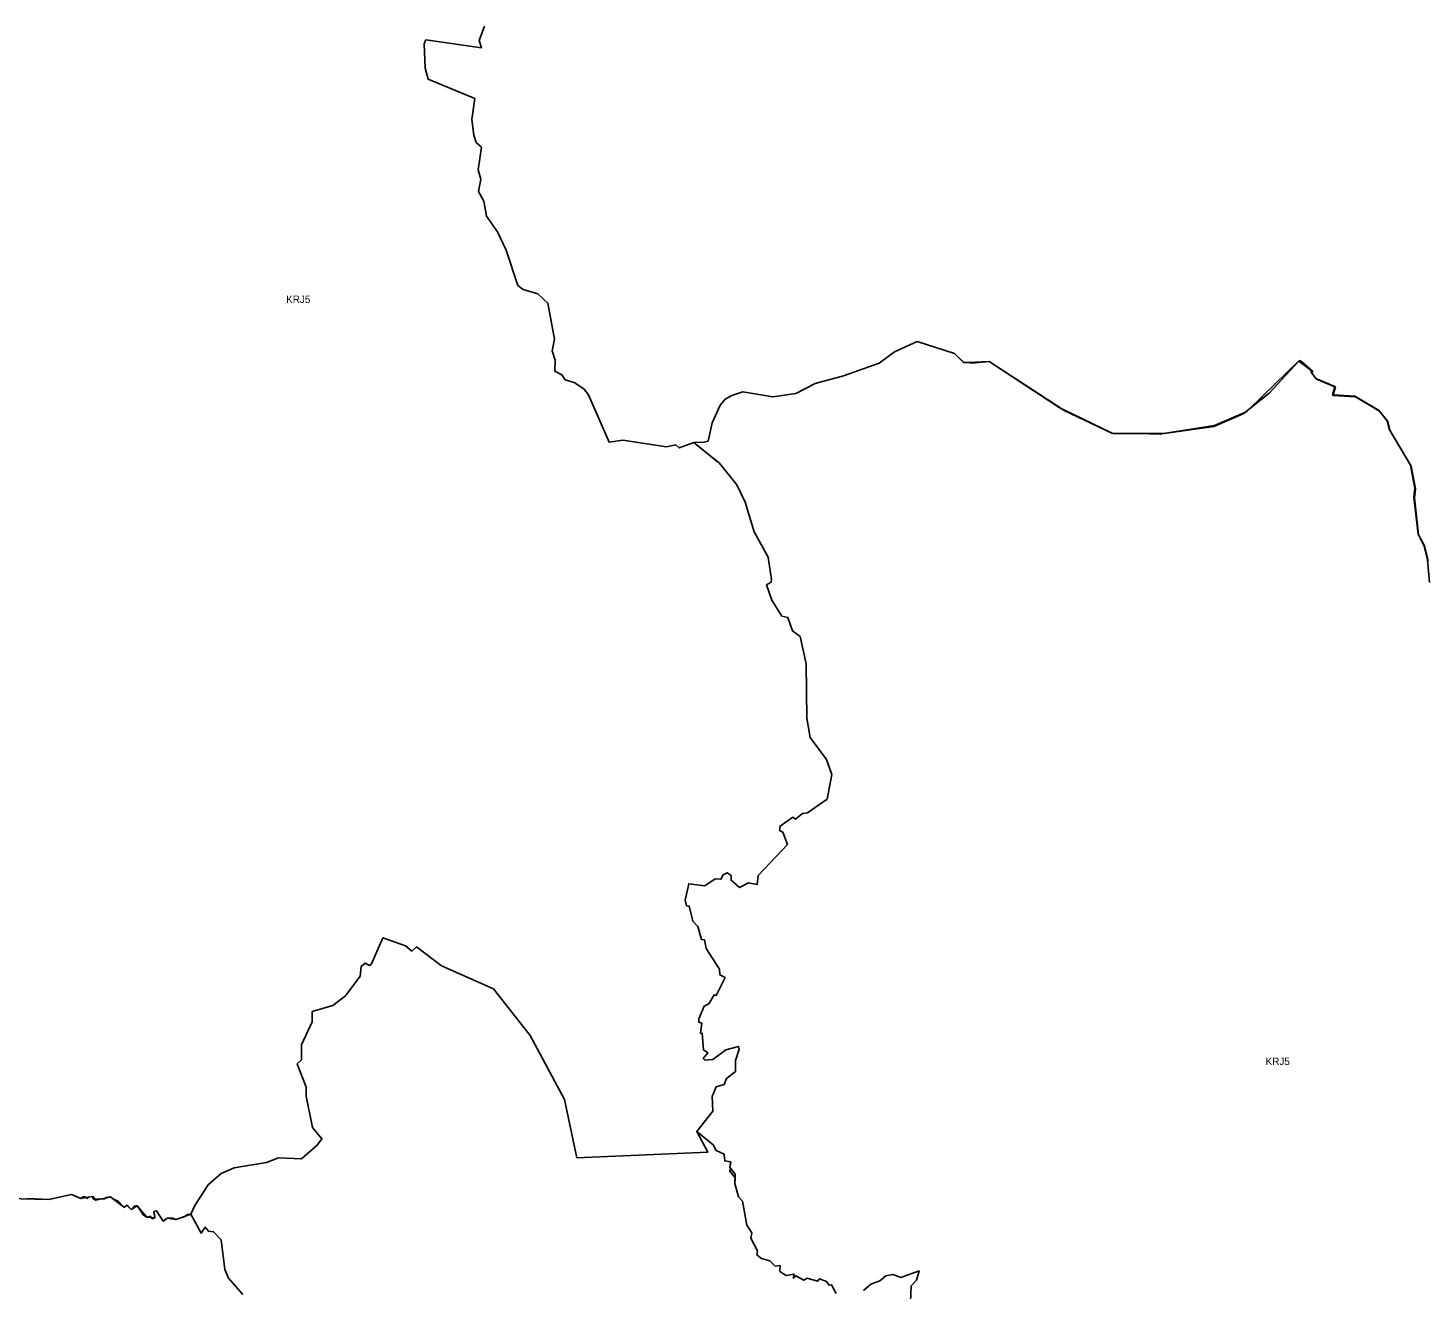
# Model space of a CAD drawing. Extents: x -563112 to -465432, y -1206259 to -1132144.
# Drawn here: x -497026 to -487557, y -1169132 to -1160601 of the extents above; entities that cross this region are included whole.
import ezdxf

# ---------------------------------------------------------------- set-up
doc = ezdxf.new("R2010")
doc.units = 0
doc.layers.add('krajiny', color=7, linetype='Continuous')

msp = doc.modelspace()

# ---------------------------------------------------------------- linework, layer by layer
at = {"layer": 'krajiny'}
for points in [[(-493937.85, -1160588.09), (-493973.85, -1160686.09), (-493959.85, -1160736.09), (-494335.14, -1160681.66), (-494345.85, -1160708.09), (-494338.85, -1160872.09), (-494319.85, -1160947.09), (-494002.85, -1161078.09), (-494023.85, -1161219.09), (-494009.85, -1161325.09), (-493993.85, -1161375.09), (-493958.85, -1161408.09), (-493981.85, -1161561.09), (-493962.85, -1161624.09), (-493979.85, -1161706.09), (-493942.85, -1161773.09), (-493923.85, -1161874.09), (-493850.95, -1161978.87), (-493792.74, -1162102.87), (-493713.16, -1162342.11), (-493676.27, -1162369.55), (-493576.66, -1162399.21), (-493509.97, -1162462.23), (-493464.03, -1162706.51), (-493480.53, -1162785.02), (-493460.61, -1162848.95), (-493463.01, -1162923.08), (-493414.33, -1162946.34), (-493393.49, -1162981.48), (-493332.46, -1162999.29), (-493267.14, -1163041.27), (-493235.27, -1163082.09), (-493095.04, -1163403.38), (-493001.9, -1163389.77), (-492708, -1163434.77), (-492644.87, -1163420.57), (-492620.67, -1163441.96), (-492522.31, -1163406.24), (-492507.27, -1163418.3), (-492425.99, -1163483.44), (-492372.72, -1163526.14), (-492351.44, -1163543.2), (-492230.83, -1163691.37), (-492175, -1163808.83), (-492113.56, -1164010.4), (-492019.9, -1164180.2), (-491996.92, -1164332.66), (-491999.73, -1164350.87), (-492031.12, -1164368.49), (-491994.07, -1164471.21), (-491927.3, -1164579.57), (-491885.76, -1164588.39), (-491854.99, -1164679.59), (-491803.95, -1164718.37), (-491762.32, -1164901.64), (-491758.79, -1165270.97), (-491735.03, -1165401.47), (-491626.32, -1165550.5), (-491589.14, -1165651.61), (-491621.71, -1165817.33), (-491752.92, -1165910.61), (-491787.11, -1165914.44), (-491833.93, -1165953.61), (-491852.71, -1165940.56), (-491939.65, -1166000.07), (-491942.11, -1166030.42), (-491920.38, -1166040.46), (-491889.7, -1166124.05), (-492087.31, -1166334.15), (-492094.04, -1166395.3), (-492153.04, -1166384.23), (-492212.68, -1166415.59), (-492270.17, -1166366.96), (-492269.94, -1166335.74), (-492297.15, -1166315.73), (-492325.16, -1166329.15), (-492339.39, -1166360.22), (-492377.57, -1166358.27), (-492448.23, -1166404.39), (-492556.51, -1166390.79), (-492580.9, -1166502.36), (-492572.26, -1166538.81), (-492553.62, -1166541.13), (-492529.53, -1166642.54), (-492495.94, -1166680.51), (-492471.63, -1166768.38), (-492449.66, -1166770.42), (-492438.27, -1166827.88), (-492349.38, -1166968.65), (-492346.74, -1167006.58), (-492311.56, -1167024.74), (-492371.29, -1167146.31), (-492384.36, -1167141.84), (-492421.47, -1167202.68), (-492453.33, -1167217.69), (-492487.8, -1167305.28), (-492488.76, -1167327.07), (-492468.55, -1167334.17), (-492476.65, -1167403.15), (-492465.98, -1167401.34), (-492457.25, -1167514.53), (-492427.15, -1167533.43), (-492458.58, -1167572.82), (-492448, -1167584.55), (-492393.32, -1167579.39), (-492306.51, -1167514.22), (-492219.47, -1167491.73), (-492216.32, -1167510.21), (-492240.47, -1167585.15), (-492240.88, -1167661.15), (-492302.54, -1167708.1), (-492318.18, -1167747.86), (-492370.41, -1167765.04), (-492398.45, -1167829.81), (-492393.28, -1167928.75), (-492503.38, -1168067.19), (-492428.69, -1168206.68), (-493313.36, -1168243.98), (-493397.24, -1167850.1), (-493630.65, -1167416.1), (-493878.65, -1167102.45), (-494230.26, -1166946.32), (-494398.21, -1166817.49), (-494430.71, -1166845.87), (-494473.8, -1166810.76), (-494625.82, -1166756.83), (-494703.02, -1166931.81), (-494716.54, -1166942.77), (-494745.54, -1166927.65), (-494773.5, -1166949.91), (-494778.32, -1167014.69), (-494877.85, -1167148.61), (-494963.39, -1167213.89), (-495104, -1167255.84), (-495103.97, -1167325.71), (-495176.06, -1167479.77), (-495177.25, -1167581.31), (-495205.36, -1167608.14), (-495144.78, -1167767.7), (-495145.69, -1167827.25), (-495102.62, -1168039.57), (-495038.23, -1168115.41), (-495069.38, -1168159.76), (-495175.35, -1168251.1), (-495330.81, -1168245.87), (-495412.89, -1168275.38), (-495631.46, -1168312.55), (-495719.31, -1168350), (-495808.49, -1168427.29), (-495897.35, -1168566.74), (-495923.87, -1168625.59), (-495948.33, -1168629.17), (-495966.84, -1168640.88), (-495969.92, -1168642.83), (-496006.42, -1168655.58), (-496026.91, -1168662.26), (-496045.93, -1168652.39), (-496056.54, -1168652.09), (-496085.17, -1168654.02), (-496094.39, -1168662.79), (-496112.7, -1168672.6), (-496156.94, -1168602.8), (-496174.26, -1168607.05), (-496171.34, -1168629), (-496168.05, -1168650.88), (-496185.55, -1168656.8), (-496191.94, -1168648.68), (-496198.68, -1168640.13), (-496221.75, -1168645.94), (-496246.48, -1168630.92), (-496262.61, -1168605.73), (-496287.33, -1168568.81), (-496296.52, -1168569.81), (-496309.11, -1168571.17), (-496327.82, -1168593.74), (-496349.96, -1168569.23), (-496355, -1168566.19), (-496356.97, -1168565), (-496375.79, -1168580.16), (-496380.47, -1168576.54), (-496380.53, -1168576.47), (-496416.39, -1168537.81), (-496447.95, -1168524.05), (-496456.56, -1168520.3), (-496467.35, -1168508.97), (-496499.42, -1168512.83), (-496503, -1168516.67), (-496507.88, -1168521.89), (-496526.46, -1168521.73), (-496534.37, -1168521.66), (-496561.51, -1168523.91), (-496567.7, -1168530.63), (-496587.01, -1168519.83), (-496586.68, -1168506.57), (-496617.69, -1168511.48), (-496617.78, -1168511.55), (-496628.15, -1168519.69), (-496634.15, -1168514.17), (-496640.07, -1168508.73), (-496652.34, -1168508.13), (-496668.1, -1168519.61), (-496731.55, -1168492.58), (-496885.21, -1168526.4), (-497029.54, -1168520.63)], [(-487547.03, -1164352.52), (-487560.1, -1164197.94), (-487585.25, -1164099.56), (-487623.83, -1164024.27), (-487651.73, -1163775.54), (-487645.06, -1163713.8), (-487674.29, -1163559.34), (-487819.32, -1163316.01), (-487832.6, -1163259.04), (-487884.25, -1163192.56), (-487888.03, -1163187.69), (-488051.52, -1163091.98), (-488197.27, -1163083.46), (-488202.35, -1163083.16), (-488187.78, -1163028.69), (-488187, -1163025.76), (-488314.55, -1162971.2), (-488348.53, -1162927.5), (-488340.23, -1162922.6), (-488338.77, -1162921.74), (-488411.75, -1162857.61), (-488425.74, -1162850.44), (-488429.52, -1162854.51), (-488630.24, -1163070.76), (-488763.09, -1163176.36), (-488791.58, -1163199), (-488807.04, -1163211.29), (-489004.27, -1163295.82), (-489342.39, -1163345.13), (-489346.21, -1163345.13), (-489517.4, -1163345.13), (-489684.77, -1163345.13), (-489692.88, -1163341.23), (-490032.92, -1163177.75), (-490051.07, -1163169.03), (-490525.81, -1162856.95), (-490641.01, -1162867.77), (-490667.95, -1162864.87), (-490699.35, -1162861.5), (-490760.55, -1162803.82), (-491012, -1162721.99), (-491165.21, -1162792.09), (-491268.75, -1162867.85), (-491509.96, -1162954.32), (-491702.03, -1163006.32), (-491831.58, -1163074.25), (-491988.33, -1163097.32), (-492191.89, -1163062.85), (-492265.34, -1163087.88), (-492310.71, -1163111.47), (-492344.96, -1163153.08), (-492398.4, -1163271.65), (-492425.04, -1163395.59), (-492453.57, -1163403.79), (-492522.31, -1163406.24), (-492620.67, -1163441.96), (-492644.87, -1163420.57), (-492708, -1163434.77), (-493001.9, -1163389.77), (-493095.04, -1163403.38), (-493235.27, -1163082.09), (-493267.14, -1163041.27), (-493332.46, -1162999.29), (-493393.49, -1162981.48), (-493414.33, -1162946.34), (-493463.01, -1162923.08), (-493460.61, -1162848.95), (-493480.53, -1162785.02), (-493464.03, -1162706.51), (-493509.97, -1162462.23), (-493576.66, -1162399.21), (-493676.27, -1162369.55), (-493713.16, -1162342.11), (-493792.74, -1162102.87), (-493850.95, -1161978.87), (-493923.85, -1161874.09), (-493942.85, -1161773.09), (-493979.85, -1161706.09), (-493962.85, -1161624.09), (-493981.85, -1161561.09), (-493958.85, -1161408.09), (-493993.85, -1161375.09), (-494009.85, -1161325.09), (-494023.85, -1161219.09), (-494002.85, -1161078.09), (-494319.85, -1160947.09), (-494338.85, -1160872.09), (-494345.85, -1160708.09), (-494335.14, -1160681.66), (-493959.85, -1160736.09), (-493973.85, -1160686.09), (-493937.85, -1160588.09)], [(-491559.92, -1169162.48), (-491590.51, -1169103.48), (-491607.97, -1169105.14), (-491625.55, -1169080.64), (-491672.12, -1169062.82), (-491685.92, -1169079.68), (-491755.54, -1169059.29), (-491779.37, -1169072.63), (-491833.21, -1169042), (-491850.05, -1169058.87), (-491844.35, -1169031.47), (-491897.55, -1169041.78), (-491939.9, -1169013.64), (-491937.54, -1168973.52), (-491971.36, -1168976.6), (-492008.14, -1168940.72), (-492065.21, -1168924.97), (-492095.78, -1168900.38), (-492091.96, -1168873.22), (-492137.63, -1168789.05), (-492129.86, -1168751.37), (-492163.79, -1168699.46), (-492193.52, -1168538.6), (-492221.05, -1168508.86), (-492245.48, -1168419.2), (-492243.08, -1168355.51), (-492278.15, -1168309.88), (-492272.79, -1168271.82), (-492313.08, -1168265.49), (-492317.03, -1168220.32), (-492371.54, -1168194.73), (-492391.49, -1168156.83), (-492503.38, -1168067.19), (-492393.28, -1167928.75), (-492398.45, -1167829.81), (-492370.41, -1167765.04), (-492318.18, -1167747.86), (-492302.54, -1167708.1), (-492240.88, -1167661.15), (-492240.47, -1167585.15), (-492216.32, -1167510.21), (-492219.47, -1167491.73), (-492306.51, -1167514.22), (-492393.32, -1167579.39), (-492448, -1167584.55), (-492458.58, -1167572.82), (-492427.15, -1167533.43), (-492457.25, -1167514.53), (-492465.98, -1167401.34), (-492476.65, -1167403.15), (-492468.55, -1167334.17), (-492488.76, -1167327.07), (-492487.8, -1167305.28), (-492453.33, -1167217.69), (-492421.47, -1167202.68), (-492384.36, -1167141.84), (-492371.29, -1167146.31), (-492311.56, -1167024.74), (-492346.74, -1167006.58), (-492349.38, -1166968.65), (-492438.27, -1166827.88), (-492449.66, -1166770.42), (-492471.63, -1166768.38), (-492495.94, -1166680.51), (-492529.53, -1166642.54), (-492553.62, -1166541.13), (-492572.26, -1166538.81), (-492580.9, -1166502.36), (-492556.51, -1166390.79), (-492448.23, -1166404.39), (-492377.57, -1166358.27), (-492339.39, -1166360.22), (-492325.16, -1166329.15), (-492297.15, -1166315.73), (-492269.94, -1166335.74), (-492270.17, -1166366.96), (-492212.68, -1166415.59), (-492153.04, -1166384.23), (-492094.04, -1166395.3), (-492087.31, -1166334.15), (-491889.7, -1166124.05), (-491920.38, -1166040.46), (-491942.11, -1166030.42), (-491939.65, -1166000.07), (-491852.71, -1165940.56), (-491833.93, -1165953.61), (-491787.11, -1165914.44), (-491752.92, -1165910.61), (-491621.71, -1165817.33), (-491589.14, -1165651.61), (-491626.32, -1165550.5), (-491735.03, -1165401.47), (-491758.79, -1165270.97), (-491762.32, -1164901.64), (-491803.95, -1164718.37), (-491854.99, -1164679.59), (-491885.76, -1164588.39), (-491927.3, -1164579.57), (-491994.07, -1164471.21), (-492031.12, -1164368.49), (-491999.73, -1164350.87), (-491996.92, -1164332.66), (-492019.9, -1164180.2), (-492113.56, -1164010.4), (-492175, -1163808.83), (-492230.83, -1163691.37), (-492351.44, -1163543.2), (-492425.99, -1163483.44), (-492522.31, -1163406.24), (-492453.57, -1163403.79), (-492425.04, -1163395.59), (-492398.4, -1163271.65), (-492344.96, -1163153.08), (-492310.71, -1163111.47), (-492265.34, -1163087.88), (-492191.89, -1163062.85), (-491988.33, -1163097.32), (-491831.58, -1163074.25), (-491702.03, -1163006.32), (-491509.96, -1162954.32), (-491268.75, -1162867.85), (-491165.21, -1162792.09), (-491012, -1162721.99), (-490760.55, -1162803.82), (-490695.5, -1162866.41), (-490667.95, -1162864.87), (-490525.81, -1162856.95), (-490032.92, -1163177.75), (-490017.75, -1163187.63), (-489696.07, -1163341.16), (-489692.88, -1163341.23), (-489517.4, -1163345.13), (-489367.08, -1163348.47), (-489346.21, -1163345.13), (-489001.53, -1163289.98), (-488791.58, -1163199), (-488782.21, -1163194.94), (-488763.09, -1163176.36), (-488430.89, -1162853.46), (-488429.52, -1162854.51), (-488340.23, -1162922.6), (-488334.92, -1162926.65), (-488344.68, -1162932.41), (-488314.53, -1162971.21), (-488310.73, -1162976.1), (-488187.78, -1163028.69), (-488183.15, -1163030.67), (-488197.27, -1163083.46), (-488198.5, -1163088.07), (-488047.67, -1163096.89), (-487884.25, -1163192.56), (-487884.18, -1163192.6), (-487828.75, -1163263.95), (-487815.47, -1163320.92), (-487670.44, -1163564.25), (-487641.21, -1163718.71), (-487647.88, -1163780.45), (-487619.98, -1164029.18), (-487581.4, -1164104.47), (-487556.25, -1164202.85)], [(-495573.82, -1169170.31), (-495668.9, -1169058.49), (-495695.33, -1168999.11), (-495720.22, -1168799.7), (-495772.52, -1168744.9), (-495805.63, -1168741.48), (-495827.58, -1168713.7), (-495855.56, -1168754.61), (-495923.87, -1168625.59), (-495897.35, -1168566.74), (-495808.49, -1168427.29), (-495719.31, -1168350), (-495631.46, -1168312.55), (-495412.89, -1168275.38), (-495330.81, -1168245.87), (-495175.35, -1168251.1), (-495069.38, -1168159.76), (-495038.23, -1168115.41), (-495102.62, -1168039.57), (-495145.69, -1167827.25), (-495144.78, -1167767.7), (-495205.36, -1167608.14), (-495177.25, -1167581.31), (-495176.06, -1167479.77), (-495103.97, -1167325.71), (-495104, -1167255.84), (-494963.39, -1167213.89), (-494877.85, -1167148.61), (-494778.32, -1167014.69), (-494773.5, -1166949.91), (-494745.54, -1166927.65), (-494716.54, -1166942.77), (-494703.02, -1166931.81), (-494625.82, -1166756.83), (-494473.8, -1166810.76), (-494430.71, -1166845.87), (-494398.21, -1166817.49), (-494230.26, -1166946.32), (-493878.65, -1167102.45), (-493630.65, -1167416.1), (-493397.24, -1167850.1), (-493313.36, -1168243.98), (-492428.69, -1168206.68), (-492503.38, -1168067.19), (-492391.49, -1168156.83), (-492371.54, -1168194.73), (-492317.03, -1168220.32), (-492313.08, -1168265.49), (-492272.79, -1168271.82), (-492278.15, -1168309.88), (-492274.76, -1168314.3), (-492243.08, -1168355.51), (-492243.99, -1168379.54), (-492245.48, -1168419.2), (-492221.05, -1168508.86), (-492193.52, -1168538.6), (-492163.79, -1168699.46), (-492129.86, -1168751.37), (-492137.63, -1168789.05), (-492091.96, -1168873.22), (-492095.78, -1168900.38), (-492065.21, -1168924.97), (-492008.14, -1168940.72), (-491971.36, -1168976.6), (-491937.54, -1168973.52), (-491939.9, -1169013.64), (-491897.55, -1169041.78), (-491844.35, -1169031.47), (-491850.05, -1169058.87), (-491833.21, -1169042), (-491779.37, -1169072.63), (-491755.54, -1169059.29), (-491685.92, -1169079.68), (-491672.12, -1169062.82), (-491625.55, -1169080.64), (-491607.97, -1169105.14), (-491590.51, -1169103.48), (-491559.92, -1169162.48)], [(-497168.1, -1168520.63), (-496885.21, -1168526.4), (-496731.55, -1168492.58), (-496668.1, -1168519.61), (-496634.15, -1168514.17), (-496617.78, -1168511.55), (-496586.68, -1168506.57), (-496567.7, -1168530.63), (-496526.46, -1168521.73), (-496503, -1168516.67), (-496467.35, -1168508.97), (-496447.95, -1168524.05), (-496380.53, -1168576.47), (-496375.79, -1168580.16), (-496356.97, -1168565), (-496327.82, -1168593.74), (-496287.33, -1168568.81), (-496221.75, -1168645.94), (-496191.94, -1168648.68), (-496168.05, -1168650.88), (-496174.26, -1168607.05), (-496156.94, -1168602.8), (-496112.7, -1168672.6), (-496085.17, -1168654.02), (-496026.91, -1168662.26), (-495966.84, -1168640.88), (-495923.87, -1168625.59), (-495855.56, -1168754.61), (-495827.58, -1168713.7), (-495805.63, -1168741.48), (-495772.52, -1168744.9), (-495720.22, -1168799.7), (-495695.33, -1168999.11), (-495668.9, -1169058.49), (-495573.82, -1169170.31)], [(-491056.07, -1169218.81), (-491051.54, -1169109.68), (-491015.37, -1169073.46), (-490999.22, -1169008.68), (-491121.8, -1169054.01), (-491177.05, -1169035.07), (-491223.98, -1169044.06), (-491263.65, -1169077.18), (-491325.01, -1169098.4), (-491375.15, -1169143.28)], [(-491375.15, -1169143.28), (-491325.01, -1169098.4), (-491263.65, -1169077.18), (-491223.98, -1169044.06), (-491177.05, -1169035.07), (-491121.8, -1169054.01), (-490999.22, -1169008.68), (-491015.37, -1169073.46), (-491051.54, -1169109.68), (-491056.07, -1169218.81)]]:
    msp.add_lwpolyline(points, dxfattribs=at)
msp.add_lwpolyline([(-492243.08, -1168355.51), (-492243.99, -1168379.54), (-492278, -1168334.84), (-492274.76, -1168314.3)], close=True, dxfattribs=at)

# ---------------------------------------------------------------- texts
for p in [(-495280.07, -1162461.51), (-488654.71, -1167617.07)]:
    msp.add_text('KRJ5', height=50, dxfattribs=at).set_placement(p)

doc.saveas('drawing.dxf')
